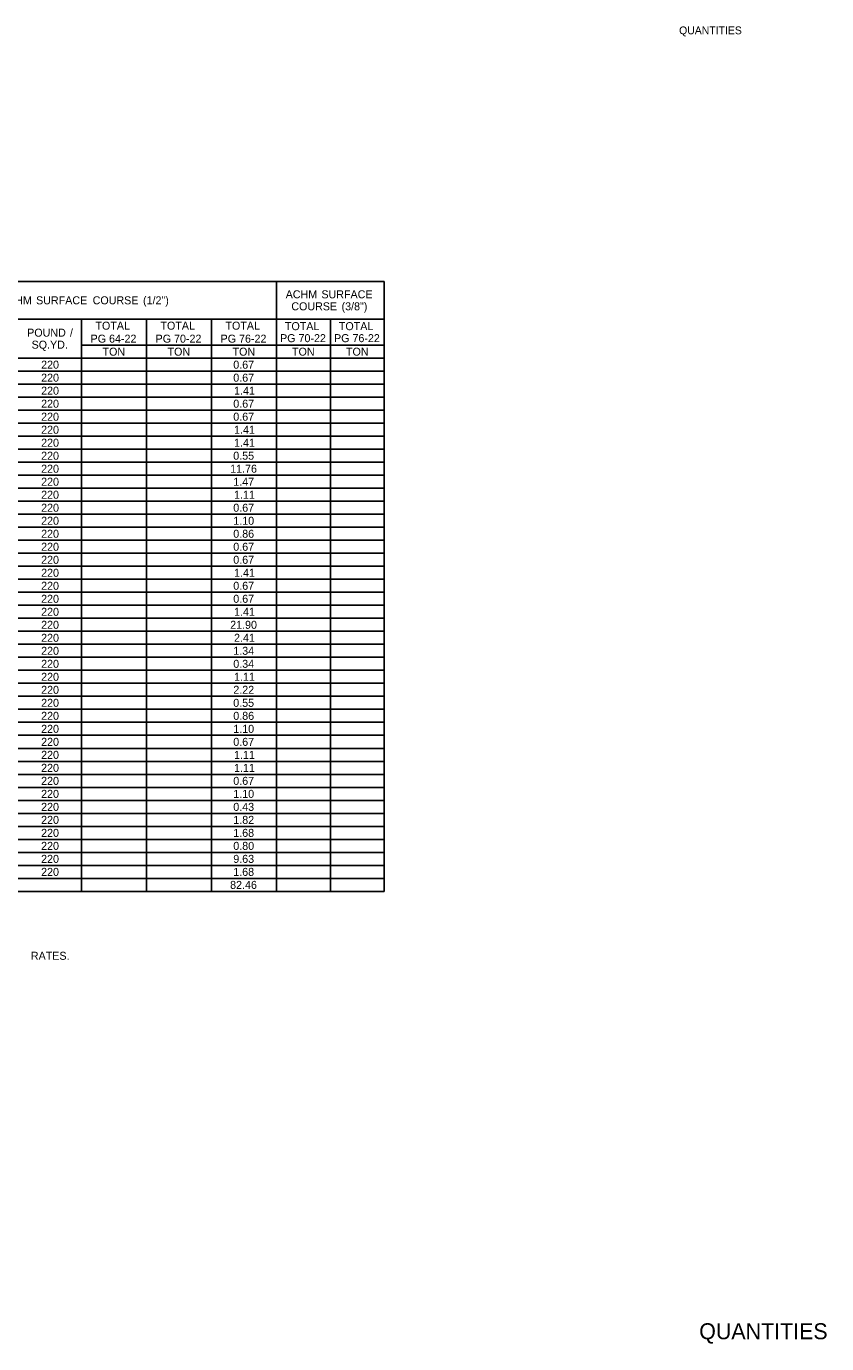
# Model space of a CAD drawing. Extents: x 540541 to 1930787, y -1948574 to 596640.
# Drawn here: x 556574 to 557174, y -1947044 to -1946056 of the extents above; entities that cross this region are included whole.
import ezdxf

# ---------------------------------------------------------------- set-up
doc = ezdxf.new("R2010")
doc.units = 0
for name, color, linetype in [('Default', 7, 'Continuous'), ('R_Border', 7, 'Continuous'), ('R_Border Prem', 7, 'Continuous')]:
    doc.layers.add(name, color=color, linetype=linetype)

msp = doc.modelspace()

# ---------------------------------------------------------------- linework, layer by layer
at = {"layer": 'Default'}
for p, q in [((555955.32, -1946247.69), (556842.08, -1946247.69)), ((556761.16, -1946704.96), (556761.16, -1946247.69)), ((556842.08, -1946704.96), (556842.08, -1946247.69)), ((556373.11, -1946275.96), (556842.08, -1946275.96)), ((556614.91, -1946704.96), (556614.91, -1946275.96)), ((556663.66, -1946704.96), (556663.66, -1946275.96)), ((556712.41, -1946704.96), (556712.41, -1946275.96)), ((556801.62, -1946704.96), (556801.62, -1946275.96)), ((556614.91, -1946295.46), (556712.41, -1946295.46)), ((556712.41, -1946295.46), (556842.08, -1946295.46)), ((556524.72, -1946305.21), (556842.08, -1946305.21)), ((556663.66, -1946695.21), (556663.66, -1946305.21)), ((556712.41, -1946695.21), (556712.41, -1946305.21)), ((556761.16, -1946695.21), (556761.16, -1946305.21)), ((556176.64, -1946314.96), (556842.08, -1946314.96)), ((556176.64, -1946324.71), (556842.08, -1946324.71)), ((556126.92, -1946334.46), (556842.08, -1946334.46)), ((556176.64, -1946344.21), (556842.08, -1946344.21)), ((556176.64, -1946353.96), (556842.08, -1946353.96)), ((556126.92, -1946363.71), (556842.08, -1946363.71)), ((556176.64, -1946373.46), (556842.08, -1946373.46)), ((556176.64, -1946383.21), (556842.08, -1946383.21)), ((556176.64, -1946392.96), (556842.08, -1946392.96)), ((556474.99, -1946402.71), (556842.08, -1946402.71)), ((556176.64, -1946412.46), (556842.08, -1946412.46)), ((556474.99, -1946422.21), (556842.08, -1946422.21)), ((556474.99, -1946431.96), (556842.08, -1946431.96)), ((556126.92, -1946441.71), (556842.08, -1946441.71)), ((556176.64, -1946451.46), (556842.08, -1946451.46)), ((556176.64, -1946461.21), (556842.08, -1946461.21)), ((556323.38, -1946470.96), (556842.08, -1946470.96)), ((556176.64, -1946480.71), (556842.08, -1946480.71)), ((556176.64, -1946490.46), (556842.08, -1946490.46)), ((556126.92, -1946500.21), (556842.08, -1946500.21)), ((556176.64, -1946509.96), (556842.08, -1946509.96)), ((556176.64, -1946519.71), (556842.08, -1946519.71)), ((556176.64, -1946529.46), (556842.08, -1946529.46)), ((556474.99, -1946539.21), (556842.08, -1946539.21)), ((556176.64, -1946548.96), (556842.08, -1946548.96)), ((556474.99, -1946558.71), (556842.08, -1946558.71)), ((556474.99, -1946568.46), (556842.08, -1946568.46)), ((556126.92, -1946578.21), (556842.08, -1946578.21)), ((556176.64, -1946587.96), (556842.08, -1946587.96)), ((556176.64, -1946597.71), (556842.08, -1946597.71)), ((556126.92, -1946607.46), (556842.08, -1946607.46)), ((556176.64, -1946617.21), (556842.08, -1946617.21)), ((556176.64, -1946626.96), (556842.08, -1946626.96)), ((555955.32, -1946636.71), (556842.08, -1946636.71)), ((556524.72, -1946636.71), (556842.08, -1946636.71)), ((556176.64, -1946646.46), (556842.08, -1946646.46)), ((556176.64, -1946656.21), (556842.08, -1946656.21)), ((556126.92, -1946665.96), (556842.08, -1946665.96)), ((556176.64, -1946675.71), (556842.08, -1946675.71)), ((556176.64, -1946685.46), (556842.08, -1946685.46)), ((555955.32, -1946695.21), (556842.08, -1946695.21)), ((556176.64, -1946704.96), (556842.08, -1946704.96))]:
    msp.add_line(p, q, dxfattribs=at)

# ---------------------------------------------------------------- texts
for s, p in [('ACHM', (556768.12, -1946260.33)), (' SURFACE', (556792.67, -1946260.33)), ('ACHM', (556554.14, -1946264.83)), (' SURFACE', (556578.69, -1946264.83)), (' COURSE', (556621.13, -1946264.83)), (' (1/2")', (556658.91, -1946264.83)), ('COURSE', (556772.34, -1946269.33)), (' (3/8")', (556807.8, -1946269.33)), ('POUND', (556574.24, -1946289.09)), (' /', (556604.1, -1946289.09)), ('TOTAL', (556625.44, -1946283.84)), ('TOTAL', (556674.19, -1946283.84)), ('TOTAL', (556722.94, -1946283.84)), ('TOTAL', (556767.54, -1946284.21)), ('TOTAL', (556808, -1946284.21)), ('SQ.YD.', (556577.58, -1946298.09)), ('PG', (556621.81, -1946293.59)), (' 64-22', (556633.42, -1946293.59)), ('PG', (556670.56, -1946293.59)), (' 70-22', (556682.17, -1946293.59)), ('PG', (556719.31, -1946293.59)), (' 76-22', (556730.92, -1946293.59)), ('PG', (556763.91, -1946293.21)), (' 70-22', (556775.52, -1946293.21)), ('PG', (556804.38, -1946293.21)), (' 76-22', (556815.98, -1946293.21)), ('TON', (556630.77, -1946303.34)), ('TON', (556679.52, -1946303.34)), ('TON', (556728.27, -1946303.34)), ('TON', (556772.87, -1946303.34)), ('TON', (556813.34, -1946303.34)), ('220', (556584.72, -1946313.09)), ('0.67', (556728.82, -1946313.09)), ('220', (556584.72, -1946322.84)), ('0.67', (556728.82, -1946322.84)), ('220', (556584.72, -1946332.59)), ('1.41', (556729.4, -1946332.59)), ('220', (556584.72, -1946342.34)), ('0.67', (556728.82, -1946342.34)), ('220', (556584.72, -1946352.09)), ('0.67', (556728.82, -1946352.09)), ('220', (556584.72, -1946361.84)), ('1.41', (556729.4, -1946361.84)), ('220', (556584.72, -1946371.59)), ('1.41', (556729.4, -1946371.59)), ('220', (556584.72, -1946381.34)), ('0.55', (556728.79, -1946381.34)), ('220', (556584.72, -1946391.09)), ('11.76', (556726.49, -1946391.09)), ('220', (556584.72, -1946400.84)), ('1.47', (556728.82, -1946400.84)), ('220', (556584.72, -1946410.59)), ('1.11', (556729.4, -1946410.59)), ('220', (556584.72, -1946420.34)), ('0.67', (556728.82, -1946420.34)), ('220', (556584.72, -1946430.09)), ('1.10', (556728.83, -1946430.09)), ('220', (556584.72, -1946439.84)), ('0.86', (556728.82, -1946439.84)), ('220', (556584.72, -1946449.59)), ('0.67', (556728.82, -1946449.59)), ('220', (556584.72, -1946459.34)), ('0.67', (556728.82, -1946459.34)), ('220', (556584.72, -1946469.09)), ('1.41', (556729.4, -1946469.09)), ('220', (556584.72, -1946478.84)), ('0.67', (556728.82, -1946478.84)), ('220', (556584.72, -1946488.59)), ('0.67', (556728.82, -1946488.59)), ('220', (556584.72, -1946498.34)), ('1.41', (556729.4, -1946498.34)), ('220', (556584.72, -1946508.09)), ('21.90', (556726.5, -1946508.09)), ('220', (556584.72, -1946517.84)), ('2.41', (556729.4, -1946517.84)), ('220', (556584.72, -1946527.59)), ('1.34', (556728.83, -1946527.59)), ('220', (556584.72, -1946537.34)), ('0.34', (556728.83, -1946537.34)), ('220', (556584.72, -1946547.09)), ('1.11', (556729.4, -1946547.09)), ('220', (556584.72, -1946556.84)), ('220', (556584.72, -1946566.59)), ('0.55', (556728.79, -1946566.59)), ('2.22', (556728.85, -1946556.84)), ('220', (556584.72, -1946576.34)), ('0.86', (556728.82, -1946576.34)), ('220', (556584.72, -1946586.09)), ('1.10', (556728.83, -1946586.09)), ('220', (556584.72, -1946595.84)), ('0.67', (556728.82, -1946595.84)), ('220', (556584.72, -1946605.59)), ('1.11', (556729.4, -1946605.59)), ('220', (556584.72, -1946615.34)), ('1.11', (556729.4, -1946615.34)), ('220', (556584.72, -1946625.09)), ('0.67', (556728.82, -1946625.09)), ('220', (556584.72, -1946634.84)), ('1.10', (556728.83, -1946634.84)), ('220', (556584.72, -1946644.59)), ('0.43', (556728.82, -1946644.59)), ('220', (556584.72, -1946654.34)), ('1.82', (556728.85, -1946654.34)), ('220', (556584.72, -1946664.09)), ('1.68', (556728.81, -1946664.09)), ('220', (556584.72, -1946673.84)), ('0.80', (556728.83, -1946673.84)), ('220', (556584.72, -1946683.59)), ('9.63', (556728.82, -1946683.59)), ('220', (556584.72, -1946693.34)), ('1.68', (556728.81, -1946693.34)), ('82.46', (556726.45, -1946703.09)), (' RATES.', (556574.8, -1946756.23))]:
    msp.add_text(s, height=6, dxfattribs=at).set_placement(p)
at = {"layer": 'R_Border'}
msp.add_text('QUANTITIES', height=12, rotation=360, dxfattribs=at).set_placement((557078.26, -1947040.71))
at = {"layer": 'R_Border Prem'}
msp.add_text('QUANTITIES', height=5.862, rotation=360, dxfattribs=at).set_placement((557063.16, -1946062.39))

doc.saveas('drawing.dxf')
